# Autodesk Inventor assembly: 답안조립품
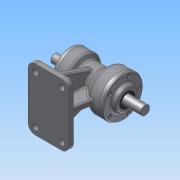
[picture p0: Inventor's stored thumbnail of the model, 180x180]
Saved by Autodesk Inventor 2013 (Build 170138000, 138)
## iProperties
Created: 2015-08
Part Number: 답안조립품
Document SubType Name: Assembly
Designer: Administrator
Author: Administrator
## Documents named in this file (10)
- C:\Users\Administrator\Desktop\450806V1033\답안조립품.iam
- C:\Users\Administrator\Desktop\450806V1033\본체.ipt
- C:\Users\Administrator\Desktop\450806V1033\M4x0.5.ipt
- C:\Users\Administrator\Desktop\450806V1033\뒤커버.ipt
- C:\Users\Administrator\Desktop\450806V1033\베어링 6203.ipt
- C:\Users\Administrator\Desktop\450806V1033\베어링 6205.ipt
- C:\Users\Administrator\Desktop\450806V1033\앞커버.ipt
- C:\Users\Administrator\Desktop\450806V1033\오일실 .ipt
- 오일실 .ipt
- C:\Users\Administrator\Desktop\450806V1033\축.ipt
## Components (10 placed, 1 different names)
1. M4x0.5:2
2. M4x0.5:3
3. M4x0.5:4
4. M4x0.5:5
5. M4x0.5:6
6. M4x0.5:1
7. M4x0.5:7
8. M4x0.5:8
9. M4x0.5:9
10. M4x0.5:10
